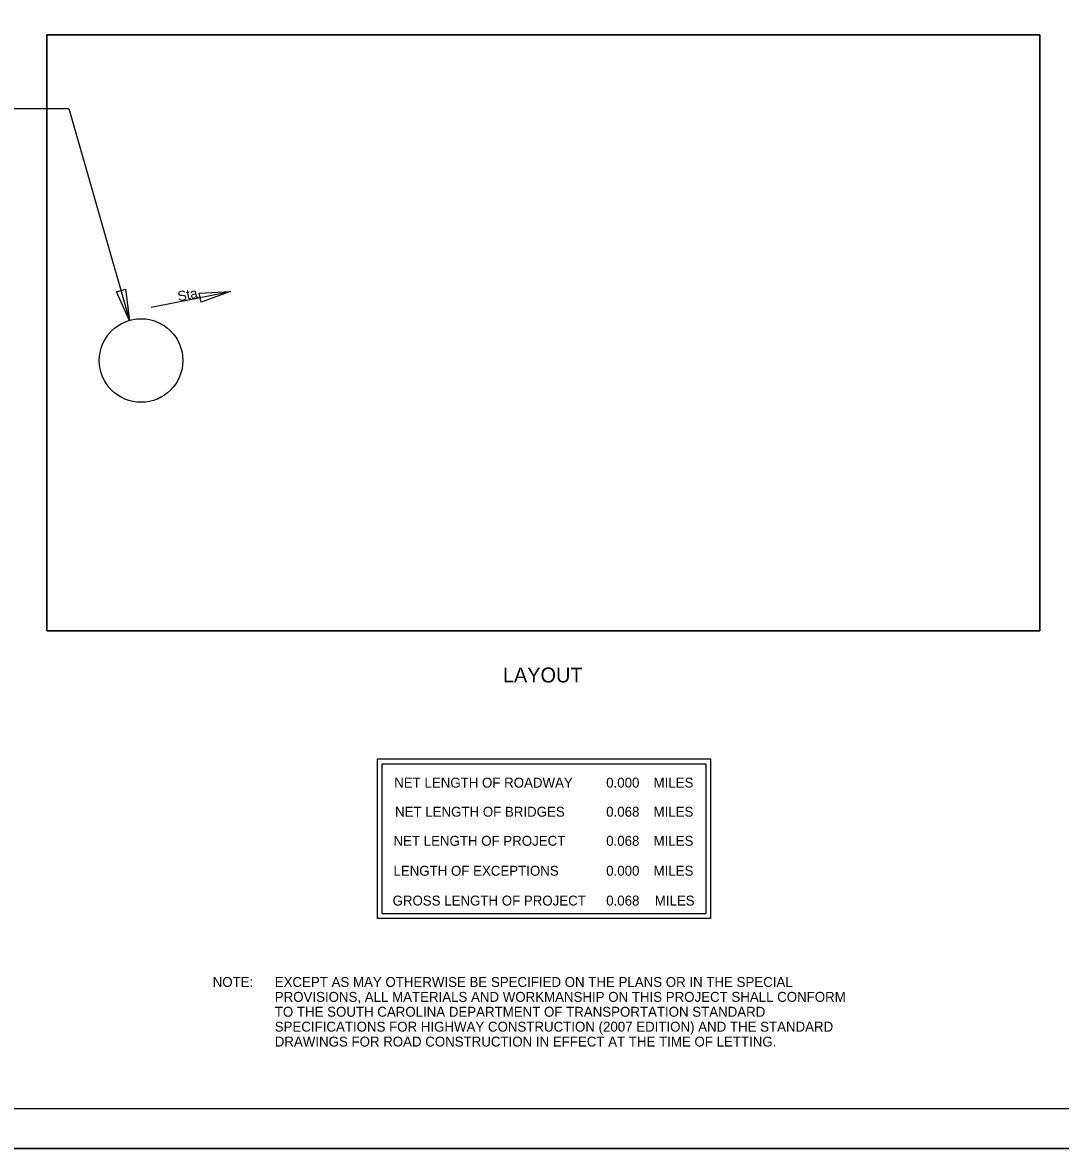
# Model space of a CAD drawing. Extents: x 297202 to 299002, y -166223 to -165123.
# Drawn here: x 297811 to 298464, y -166223 to -165515 of the extents above; entities that cross this region are included whole.
import ezdxf

# ---------------------------------------------------------------- set-up
doc = ezdxf.new("R2010")
doc.units = 0
for name, color, linetype in [('BR_AUTO DIMENSION', 7, 'Continuous'), ('BR_BORDER LINES', 7, 'Continuous'), ('BR_DETAILS', 7, 'Continuous'), ('BR_SITE LOCATION', 7, 'Continuous'), ('BR_TABLE LINES', 7, 'Continuous'), ('BR_TEXT', 7, 'Continuous'), ('GN_TitleSheetMap', 7, 'Continuous'), ('RD_SHT_IplotShp', 7, 'Continuous')]:
    doc.layers.add(name, color=color, linetype=linetype)

msp = doc.modelspace()

# ---------------------------------------------------------------- linework, layer by layer
at = {"layer": 'BR_AUTO DIMENSION'}
for points in [[(297875.68, -165682.45), (297878.26, -165702.03), (297870.05, -165684.06)], [(297922.11, -165684.86), (297941.84, -165683.94), (297923.24, -165690.6)]]:
    msp.add_lwpolyline(points, close=True, dxfattribs=at)
at = {"layer": 'BR_BORDER LINES'}
for p, q in [((297301.63, -166198), (298976.63, -166198)), ((297201.63, -166223), (299001.63, -166223))]:
    msp.add_line(p, q, dxfattribs=at)
at = {"layer": 'BR_DETAILS'}
for p, q in [((298244.13, -165978.22), (298034.13, -165978.22)), ((298034.13, -165978.22), (298034.13, -166078.17)), ((298244.13, -166078.22), (298244.13, -165978.22)), ((298241.13, -165981.22), (298037.13, -165981.22)), ((298037.13, -165981.22), (298037.13, -166075.22)), ((298241.13, -166075.27), (298241.13, -165981.22)), ((298034.13, -166078.22), (298244.13, -166078.22)), ((298037.13, -166075.22), (298241.13, -166075.22))]:
    msp.add_line(p, q, dxfattribs=at)
at = {"layer": 'BR_SITE LOCATION'}
msp.add_lwpolyline([(297799.37, -165568.7), (297839.94, -165568.7), (297878.26, -165702.03)], dxfattribs=at)
msp.add_circle((297885.52, -165727.3), 26.29, dxfattribs=at)
at = {"layer": 'BR_TABLE LINES'}
msp.add_line((297891.82, -165693.83), (297941.84, -165683.94), dxfattribs=at)
at = {"layer": 'GN_TitleSheetMap'}
for points in [[(297826.29, -165522.47), (298451.29, -165522.47), (298451.29, -165897.47), (297826.29, -165897.47)], [(297826.29, -165897.47), (298451.29, -165897.47), (298451.29, -165522.47), (297826.29, -165522.47)]]:
    msp.add_lwpolyline(points, close=True, dxfattribs=at)
at = {"layer": 'RD_SHT_IplotShp'}
msp.add_lwpolyline([(297201.63, -165123.07), (299001.63, -165123.07), (299001.63, -166223.07), (297201.63, -166223.07)], close=True, dxfattribs=at)

# ---------------------------------------------------------------- texts
at = {"layer": 'BR_DETAILS'}
for s, height, p in [('LAYOUT', 9.375, (298113.26, -165929.86)), ('NET LENGTH OF ROADWAY', 6.25, (298044.88, -165996.02)), ('MILES', 6.25, (298208.12, -165996.02)), ('NET LENGTH OF BRIDGES', 6.25, (298045.38, -166014.32)), ('MILES', 6.25, (298208.11, -166014.32)), ('NET LENGTH OF PROJECT', 6.25, (298044.38, -166032.62)), ('MILES', 6.25, (298208.11, -166032.62)), ('LENGTH OF EXCEPTIONS', 6.25, (298044.38, -166051.47)), ('MILES', 6.25, (298208.13, -166051.47)), ('GROSS LENGTH OF PROJECT', 6.25, (298043.83, -166070.22)), ('MILES', 6.25, (298208.88, -166070.22)), ('NOTE:', 6.25, (297930.58, -166121.44)), ('EXCEPT AS MAY OTHERWISE BE SPECIFIED ON THE PLANS OR IN THE SPECIAL ', 6.25, (297969.67, -166121.44)), ('PROVISIONS, ALL MATERIALS AND WORKMANSHIP ON THIS PROJECT SHALL CONFORM ', 6.25, (297969.67, -166130.81)), ('TO THE SOUTH CAROLINA DEPARTMENT OF TRANSPORTATION STANDARD ', 6.25, (297969.67, -166140.19)), ('SPECIFICATIONS FOR HIGHWAY CONSTRUCTION (2007 EDITION) AND THE STANDARD', 6.25, (297969.67, -166149.56)), ('DRAWINGS FOR ROAD CONSTRUCTION IN EFFECT AT THE TIME OF LETTING.', 6.25, (297969.67, -166158.94))]:
    msp.add_text(s, height=height, dxfattribs=at).set_placement(p)
at = {"layer": 'BR_TEXT'}
msp.add_text('Sta.', height=6.25, rotation=11.18362, dxfattribs=at).set_placement((297909.21, -165690.09))
for s, p in [('0.000', (298178.3, -165996.02)), ('0.068', (298178.3, -166014.32)), ('0.068', (298178.3, -166032.62)), ('0.000', (298178.3, -166051.47)), ('0.068', (298178.3, -166070.22))]:
    msp.add_text(s, height=6.25, dxfattribs=at).set_placement(p)

doc.saveas('drawing.dxf')
